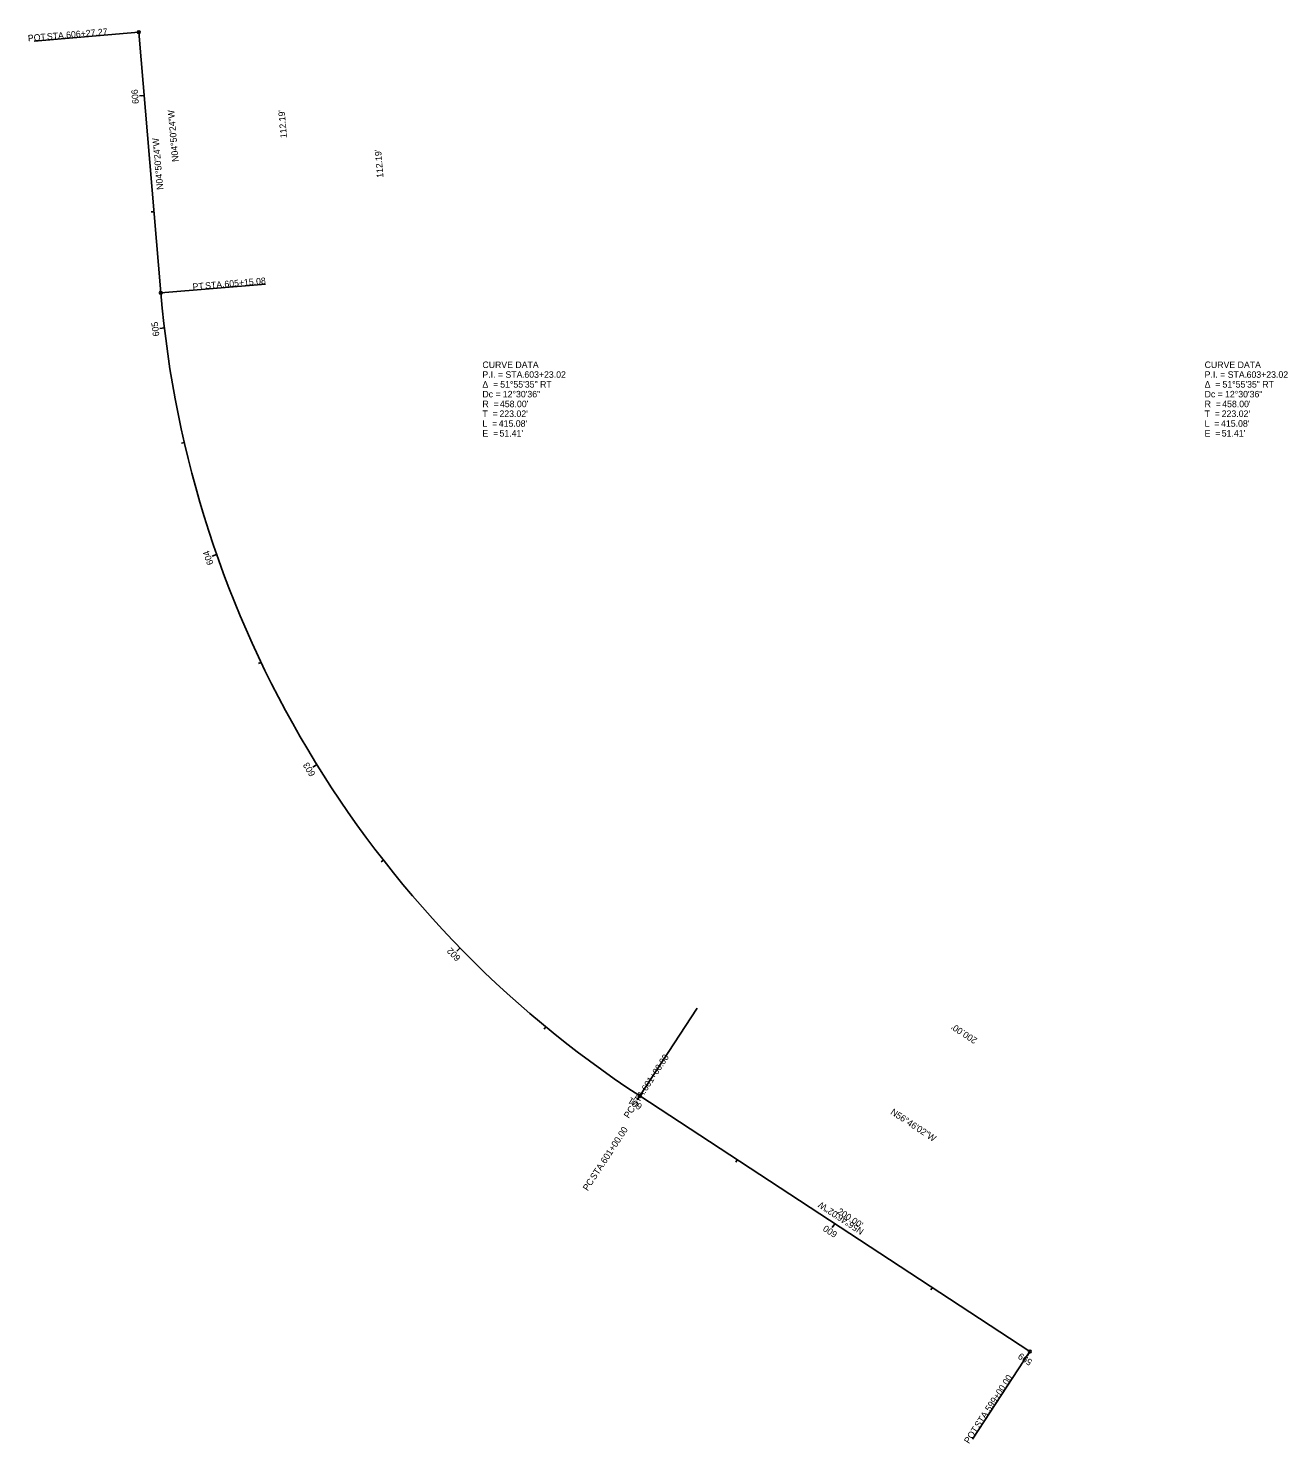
# Model space of a CAD drawing. Extents: x 1507135 to 1508660, y 327655 to 329219.
# Drawn here: x 1508120 to 1508660, y 327655 to 328262 of the extents above; entities that cross this region are included whole.
import ezdxf

# ---------------------------------------------------------------- set-up
doc = ezdxf.new("R2010")
doc.units = 0
for name, color, linetype in [('GE_X_Alignment', 7, 'Continuous'), ('GE_X_Alignment_100_Bearings', 7, 'Continuous'), ('GE_X_Alignment_100_Cardinal_Points', 7, 'Continuous'), ('GE_X_Alignment_100_Curve_Data', 7, 'Continuous'), ('GE_X_Alignment_100_Distances', 7, 'Continuous'), ('GE_X_Alignment_100_Stations', 7, 'Continuous'), ('GE_X_Alignment_500_Bearings', 7, 'Continuous'), ('GE_X_Alignment_500_Cardinal_Points', 7, 'Continuous'), ('GE_X_Alignment_500_Curve_Data', 7, 'Continuous'), ('GE_X_Alignment_500_Distances', 7, 'Continuous'), ('GE_X_Alignment_500_Stations', 7, 'Continuous')]:
    doc.layers.add(name, color=color, linetype=linetype)

msp = doc.modelspace()

# ---------------------------------------------------------------- linework, layer by layer
at = {"layer": 'GE_X_Alignment'}
for p, q in [((1508176.37, 328148.49), (1508166.91, 328260.27)), ((1508549.02, 327694.43), (1508381.73, 327804.04))]:
    msp.add_line(p, q, dxfattribs=at)
msp.add_arc((1508632.74, 328187.13), 458, 184.84043, 236.76696, dxfattribs=at)
at = {"layer": 'GE_X_Alignment_100_Cardinal_Points'}
for p, q in [((1508176.37, 328148.49), (1508221.21, 328152.28)), ((1508381.73, 327804.04), (1508406.4, 327841.68)), ((1508549.02, 327694.43), (1508524.36, 327656.79))]:
    msp.add_line(p, q, dxfattribs=at)
for centre in [(1508176.37, 328148.49), (1508381.73, 327804.04), (1508549.02, 327694.43)]:
    msp.add_circle(centre, 0.6, dxfattribs=at)
at = {"layer": 'GE_X_Alignment_100_Stations'}
for p, q in [((1508169.21, 328233.1), (1508167.21, 328232.94)), ((1508173.43, 328183.28), (1508172.23, 328183.18)), ((1508177.89, 328133.48), (1508175.9, 328133.25)), ((1508186.44, 328084.25), (1508185.27, 328083.98)), ((1508200.31, 328036.23), (1508198.42, 328035.57)), ((1508219.33, 327990.02), (1508218.24, 327989.5)), ((1508243.26, 327946.15), (1508241.56, 327945.1)), ((1508271.84, 327905.15), (1508270.89, 327904.41)), ((1508304.71, 327867.51), (1508303.28, 327866.11)), ((1508341.49, 327833.67), (1508340.72, 327832.74)), ((1508381.73, 327804.04), (1508380.64, 327802.37)), ((1508423.56, 327776.64), (1508422.9, 327775.63)), ((1508465.38, 327749.24), (1508464.28, 327747.56)), ((1508507.2, 327721.83), (1508506.54, 327720.83)), ((1508549.02, 327694.43), (1508547.93, 327692.76))]:
    msp.add_line(p, q, dxfattribs=at)
at = {"layer": 'GE_X_Alignment_500_Cardinal_Points'}
for p, q in [((1508166.91, 328260.27), (1508122.07, 328256.48)), ((1508176.37, 328148.49), (1508221.21, 328152.28)), ((1508381.73, 327804.04), (1508406.4, 327841.68)), ((1508549.02, 327694.43), (1508524.36, 327656.79))]:
    msp.add_line(p, q, dxfattribs=at)
for centre in [(1508166.91, 328260.27), (1508176.37, 328148.49), (1508381.73, 327804.04), (1508549.02, 327694.43)]:
    msp.add_circle(centre, 0.6, dxfattribs=at)
at = {"layer": 'GE_X_Alignment_500_Stations'}
for p, q in [((1508169.21, 328233.1), (1508168.01, 328233)), ((1508177.89, 328133.48), (1508175.9, 328133.25)), ((1508200.31, 328036.23), (1508199.18, 328035.84)), ((1508243.26, 327946.15), (1508242.24, 327945.52)), ((1508304.71, 327867.51), (1508303.85, 327866.67)), ((1508381.73, 327804.04), (1508381.08, 327803.04)), ((1508465.38, 327749.24), (1508464.28, 327747.56)), ((1508549.02, 327694.43), (1508548.37, 327693.43))]:
    msp.add_line(p, q, dxfattribs=at)

# ---------------------------------------------------------------- texts
at = {"layer": 'GE_X_Alignment_100_Bearings'}
for s, rotation, p in [('N04°50\'24"W', 94.84008, (1508184.03, 328204.8)), ('N56°46\'02"W', 326.76731, (1508489, 327796.48))]:
    msp.add_text(s, height=2.8, rotation=rotation, dxfattribs=at).set_placement(p)
at = {"layer": 'GE_X_Alignment_100_Cardinal_Points'}
for s, rotation, p in [('PT', 4.84008, (1508190.13, 328149.69)), (' STA. ', 4.84008, (1508194.46, 328150.06)), ('605+15.08', 4.84008, (1508203.75, 328150.84)), ('601+00.00', 56.76696, (1508384.65, 327805.86)), (' STA. ', 56.76696, (1508379.54, 327798.06)), ('PC', 56.76696, (1508377.02, 327794.21)), ('599+00.00', 56.76731, (1508531.92, 327668.4)), (' STA. ', 56.76731, (1508526.81, 327660.6)), ('POT', 56.76731, (1508522.9, 327654.64))]:
    msp.add_text(s, height=2.8, rotation=rotation, dxfattribs=at).set_placement(p)
at = {"layer": 'GE_X_Alignment_100_Curve_Data'}
for s, p in [('CURVE DATA', (1508314.27, 328116.25)), ('P.I. = STA. ', (1508314.27, 328112.05)), ('603+23.02', (1508332.26, 328112.05)), ('Δ  = ', (1508314.27, 328107.85)), ('51°55\'35" RT', (1508321.91, 328107.85)), ('Dc = ', (1508314.27, 328103.65)), ('12°30\'36"', (1508323.01, 328103.65)), ('T  = ', (1508314.27, 328095.25)), ('R  = ', (1508314.27, 328099.45)), ("223.02'", (1508321.58, 328095.25)), ("458.00'", (1508321.8, 328099.45)), ('L  = ', (1508314.27, 328091.05)), ("415.08'", (1508321.3, 328091.05)), ('E  = ', (1508314.27, 328086.85)), ("51.41'", (1508321.61, 328086.85))]:
    msp.add_text(s, height=2.8, dxfattribs=at).set_placement(p)
at = {"layer": 'GE_X_Alignment_100_Distances'}
for s, rotation, p in [("112.19'", 94.84008, (1508230.51, 328214.97)), ("200.00'", 326.76731, (1508466.12, 327753.83))]:
    msp.add_text(s, height=2.8, rotation=rotation, dxfattribs=at).set_placement(p)
at = {"layer": 'GE_X_Alignment_100_Stations'}
for s, rotation, p in [('606', 94.84008, (1508166.99, 328229.65)), ('605', 96.72698, (1508175.78, 328130.01)), ('604', 109.23697, (1508199.03, 328032.31)), ('603', 121.74697, (1508242.82, 327942.11)), ('602', 134.25696, (1508305.16, 327863.46)), ('601', 146.76731, (1508383.06, 327800.18)), ('600', 146.76731, (1508466.74, 327745.35)), ('599', 146.76731, (1508550.35, 327690.57))]:
    msp.add_text(s, height=2.8, rotation=rotation, dxfattribs=at).set_placement(p)
at = {"layer": 'GE_X_Alignment_500_Bearings'}
for s, rotation, p in [('N04°50\'24"W', 94.84008, (1508177.44, 328192.8)), ('N56°46\'02"W', 146.76731, (1508478.07, 327746.66))]:
    msp.add_text(s, height=2.8, rotation=rotation, dxfattribs=at).set_placement(p)
at = {"layer": 'GE_X_Alignment_500_Cardinal_Points'}
for s, rotation, p in [(' STA. ', 4.84008, (1508126.6, 328256.9)), ('606+27.27', 4.84008, (1508135.89, 328257.69)), ('POT', 4.84008, (1508119.5, 328256.3)), ('PT', 4.84008, (1508190.13, 328149.69)), (' STA. ', 4.84008, (1508194.46, 328150.06)), ('605+15.08', 4.84008, (1508203.75, 328150.84)), ('601+00.00', 56.76696, (1508367.05, 327774.75)), (' STA. ', 56.76696, (1508361.94, 327766.95)), ('PC', 56.76696, (1508359.42, 327763.1)), ('599+00.00', 56.76731, (1508531.92, 327668.4)), (' STA. ', 56.76731, (1508526.81, 327660.6)), ('POT', 56.76731, (1508522.9, 327654.64))]:
    msp.add_text(s, height=2.8, rotation=rotation, dxfattribs=at).set_placement(p)
at = {"layer": 'GE_X_Alignment_500_Curve_Data'}
for s, p in [('CURVE DATA', (1508623.95, 328116.25)), ('P.I. = STA. ', (1508623.95, 328112.05)), ('603+23.02', (1508641.95, 328112.05)), ('Δ  = ', (1508623.95, 328107.85)), ('51°55\'35" RT', (1508631.6, 328107.85)), ('Dc = ', (1508623.95, 328103.65)), ('12°30\'36"', (1508632.7, 328103.65)), ('T  = ', (1508623.95, 328095.25)), ('R  = ', (1508623.95, 328099.45)), ("223.02'", (1508631.27, 328095.25)), ("458.00'", (1508631.49, 328099.45)), ('L  = ', (1508623.95, 328091.05)), ("415.08'", (1508630.99, 328091.05)), ('E  = ', (1508623.95, 328086.85)), ("51.41'", (1508631.3, 328086.85))]:
    msp.add_text(s, height=2.8, dxfattribs=at).set_placement(p)
at = {"layer": 'GE_X_Alignment_500_Distances'}
for s, rotation, p in [("112.19'", 94.84008, (1508271.86, 328197.96)), ("200.00'", 146.76731, (1508526.72, 327828.53))]:
    msp.add_text(s, height=2.8, rotation=rotation, dxfattribs=at).set_placement(p)
at = {"layer": 'GE_X_Alignment_500_Stations'}
for s, rotation, p in [('605', 96.72698, (1508175.78, 328130.01)), ('600', 146.76731, (1508466.74, 327745.35))]:
    msp.add_text(s, height=2.8, rotation=rotation, dxfattribs=at).set_placement(p)

doc.saveas('drawing.dxf')
